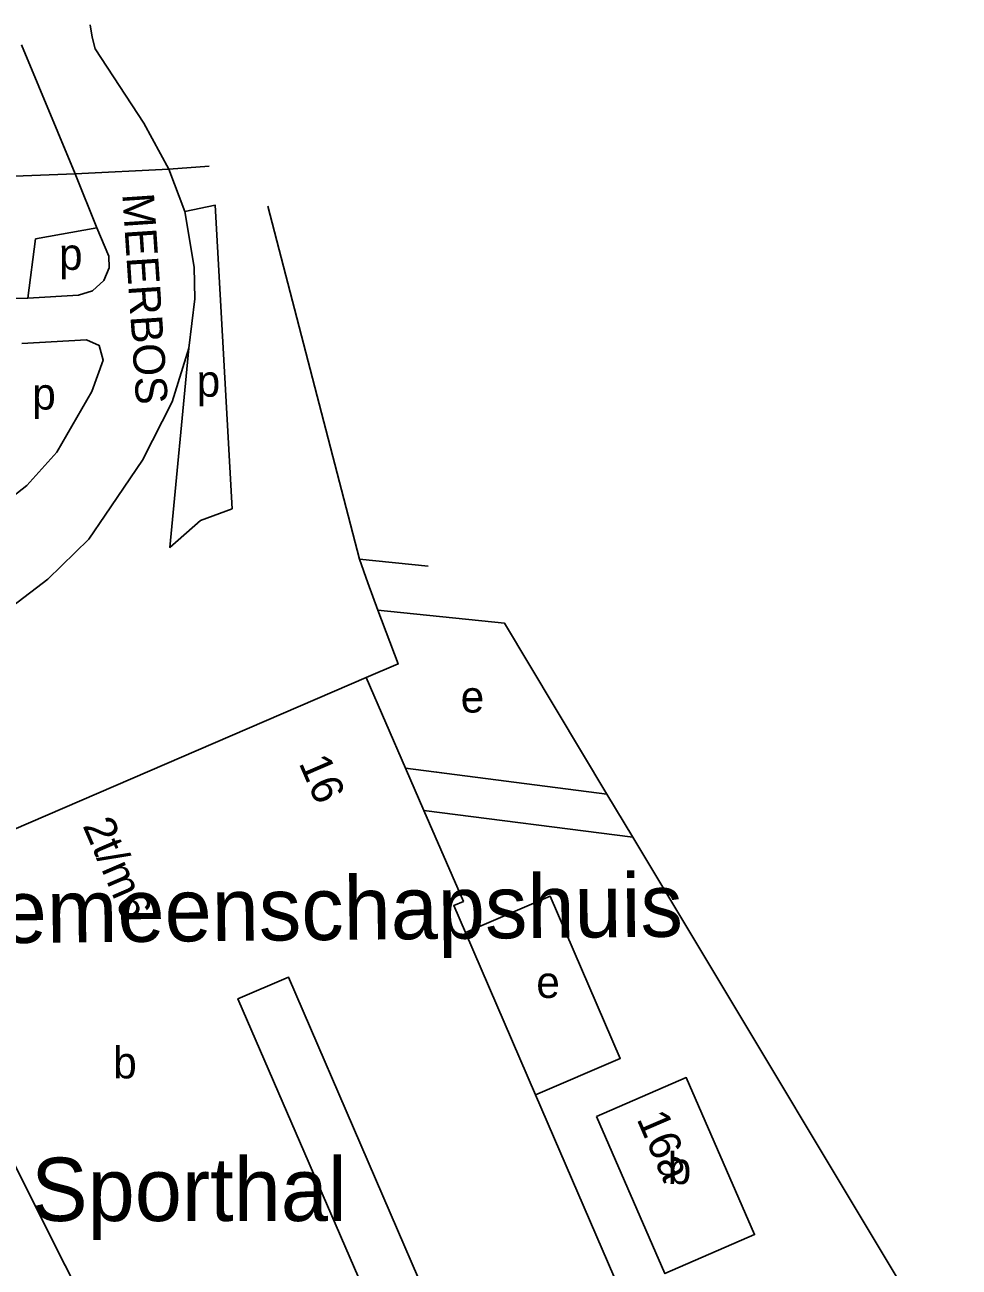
# Model space of a CAD drawing. Extents: x 155696 to 157795, y 382328 to 384028.
# Drawn here: x 156637.4 to 156755.3, y 383706.4 to 383863.2 of the extents above; entities that cross this region are included whole.
import ezdxf

# ---------------------------------------------------------------- set-up
doc = ezdxf.new("R2010")
doc.units = 0
for name, color, linetype in [('BLT_Basislijn', 7, 'Continuous'), ('BLT_Bebouwing', 7, 'Continuous'), ('BLT_Bebouwing_beschrifting', 7, 'Continuous'), ('BLT_Centroide', 7, 'Continuous'), ('BLT_Huisnummer', 7, 'Continuous'), ('BLT_Huisnummer_reeks', 7, 'Continuous'), ('BLT_Straatnaam_verkleind', 7, 'Continuous'), ('BLT_Vlakafsluiter', 7, 'Continuous')]:
    doc.layers.add(name, color=color, linetype=linetype)

msp = doc.modelspace()

# ---------------------------------------------------------------- linework, layer by layer
at = {"layer": 'BLT_Basislijn'}
for p, q in [((156643.73, 383844.42), (156646.46, 383837.62)), ((156657.58, 383839.67), (156655.58, 383845.03)), ((156638.73, 383836.22), (156637.77, 383828.73)), ((156637.77, 383828.73), (156633.62, 383828.7)), ((156679.64, 383795.78), (156680.68, 383792.79)), ((156680.68, 383792.79), (156681.96, 383789.33)), ((156710.87, 383766.11), (156685.45, 383769.37)), ((156690.34, 383768.74), (156689.39, 383768.86)), ((156714.14, 383760.65), (156687.76, 383764.03))]:
    msp.add_line(p, q, dxfattribs=at)
for points in [[(156655.58, 383845.03), (156652.4, 383850.82), (156646.27, 383860.21), (156645.88, 383861.67), (156645.65, 383863.24)], [(156643.73, 383844.42), (156636.98, 383860.73)], [(156655.58, 383845.03), (156660.65, 383845.41)], [(156632.77, 383844.01), (156643.73, 383844.42)], [(156657.58, 383839.67), (156661.43, 383840.45), (156663.54, 383802.13), (156659.55, 383800.67), (156655.68, 383797.25), (156658.1, 383822.4)], [(156658.1, 383822.4), (156658.84, 383828.65), (156658.76, 383832.64), (156657.58, 383839.67)], [(156668.06, 383840.33), (156679.64, 383795.78)], [(156637.77, 383828.73), (156644.17, 383829.11), (156645.94, 383829.64), (156647.35, 383830.95), (156648.04, 383832.57), (156647.98, 383834.05), (156646.46, 383837.62)], [(156646.46, 383837.62), (156638.73, 383836.22)], [(156635.09, 383803.03), (156637.62, 383805.08), (156641.42, 383809.29), (156645.85, 383816.95), (156647.27, 383820.91), (156646.79, 383822.73), (156645.16, 383823.46), (156637.01, 383823.01)], [(156635.84, 383789.82), (156640.27, 383793.23), (156645.47, 383798.28), (156647.51, 383801.34), (156652.24, 383808.26), (156656, 383815.65), (156658.1, 383822.4)], [(156679.64, 383795.78), (156688.3, 383794.89)], [(156681.96, 383789.33), (156684.52, 383782.54), (156680.48, 383780.83)], [(156710.87, 383766.11), (156697.94, 383787.67), (156681.96, 383789.33)], [(156755.33, 383691.98), (156714.14, 383760.65)], [(156693.01, 383748.61), (156703.69, 383753.23), (156712.54, 383732.73), (156701.86, 383728.12)]]:
    msp.add_lwpolyline(points, dxfattribs=at)
at = {"layer": 'BLT_Bebouwing'}
for p, q in [((156680.48, 383780.83), (156620.33, 383754.86)), ((156680.48, 383780.83), (156685.45, 383769.37)), ((156701.86, 383728.12), (156693.01, 383748.61))]:
    msp.add_line(p, q, dxfattribs=at)
for points in [[(156685.45, 383769.37), (156687.76, 383764.03)], [(156693.01, 383748.61), (156691.53, 383752.02), (156692.74, 383752.54), (156687.76, 383764.03)], [(156652.41, 383686.74), (156632.48, 383726.5), (156620.33, 383754.86)], [(156700.86, 383673.02), (156670.66, 383743), (156664.29, 383740.25), (156686.22, 383689.51), (156663.44, 383679.68)], [(156701.86, 383728.12), (156721.75, 383682.04), (156700.86, 383673.02)]]:
    msp.add_lwpolyline(points, dxfattribs=at)
msp.add_lwpolyline([(156709.55, 383725.4), (156720.88, 383730.3), (156729.51, 383710.48), (156718.19, 383705.56)], close=True, dxfattribs=at)
at = {"layer": 'BLT_Vlakafsluiter'}
for p, q in [((156643.73, 383844.42), (156655.58, 383845.03)), ((156710.87, 383766.11), (156714.14, 383760.65))]:
    msp.add_line(p, q, dxfattribs=at)

# ---------------------------------------------------------------- texts
at = {"layer": 'BLT_Bebouwing_beschrifting'}
msp.add_text('Gemeenschapshuis', height=8, rotation=0.5505, dxfattribs=at).set_placement((156625.93, 383747.2))
msp.add_text('Sporthal', height=8, dxfattribs=at).set_placement((156638.18, 383712.19))
at = {"layer": 'BLT_Centroide'}
for s, p in [('p', (156641.7, 383832.3)), ('p', (156659.08, 383816.28)), ('p', (156638.32, 383814.66)), ('e', (156692.4, 383776.4)), ('e', (156701.95, 383740.36)), ('b', (156648.54, 383730.2)), ('b', (156718.54, 383716.86))]:
    msp.add_text(s, height=4, dxfattribs=at).set_placement(p)
at = {"layer": 'BLT_Huisnummer'}
msp.add_text('16a', height=4, rotation=293.3306, dxfattribs=at).set_placement((156714.57, 383725.1))
at = {"layer": 'BLT_Huisnummer_reeks'}
for s, p in [('16', (156671.92, 383770.04)), ('2t/m6', (156644.64, 383762.13))]:
    msp.add_text(s, height=4, rotation=293.3306, dxfattribs=at).set_placement(p)
at = {"layer": 'BLT_Straatnaam_verkleind'}
msp.add_text('MEERBOS', height=4, rotation=273.8215, dxfattribs=at).set_placement((156649.68, 383841.88))

doc.saveas('drawing.dxf')
